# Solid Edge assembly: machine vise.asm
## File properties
Author: Deepak Maini
Template: Normal.asm
Last saved by: MYPC
Revision: 23
Application: Solid Edge
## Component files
slide key.par
base.par
Sliding jaw.par
vise screw.par
collar.par
handle rod.par
handle ball.par
jaw plate.par
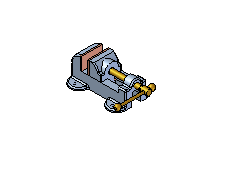
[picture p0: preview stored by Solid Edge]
